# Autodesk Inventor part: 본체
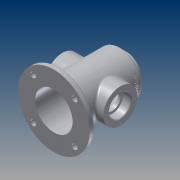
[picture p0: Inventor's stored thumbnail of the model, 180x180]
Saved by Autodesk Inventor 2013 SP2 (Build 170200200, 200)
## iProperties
Created: 2014-12
Part Number: 본체
Material: 알루미늄 6061
Document SubType Name: Modeling
Designer: CADB303
Density: 2.71 g/cm^3
Mass: 479.262 g
Surface Area: 608.932 cm^2
Volume: 176.85 cm^3
Author: CADB303
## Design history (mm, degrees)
sketch "스케치1"
  geometry: L1 (0, 53)-(0, -53); L2 (0, -53)-(-52.5, -53); L3 (-52.5, -53)-(-52.5, -45); L4 (-52.5, -45)-(-32.5, -45); L5 (-32.5, -45)-(-32.5, 45); L6 (-32.5, 45)-(-22.5, 45); L7 (-22.5, 45)-(-22.5, 53); L8 (-22.5, 53)-(0, 53); L9 (0, 40)-(-27.5, 40); L10 (-27.5, 40)-(-27.5, -53); 2 further points
  constraints: 20 end point, 6 parallel, 3 perpendicular, 2 point on line, 1 coincident, 1 midpoint, 1 vertical
  dimensions: "d0" = 106 distance of L1.start L1.end; "d2" = 98 distance between parallel lines of L6 L2; "d3" = 93 distance between parallel lines of L9 L2; "d4" = 45 diameter of L7.end L1; "d5" = 65 diameter of L5 L1; "d6" = 55 diameter of L10 L1; "d7" = 8 distance between parallel lines of L4 L2; "d8" = 105 diameter of L3 L1
revolve "회전1" sketch "스케치1" stored, may be unused: angle "d9" = 90 deg
node "작업 평면1"
sketch "스케치2"
  geometry: L1 (-53, -52.5)-(-53, 52.5) reference; C1 r 25 at (2, 0); 1 further point
  constraints: 1 centre point, 1 horizontal alignment
  dimensions: "d15" = 50 diameter of C1; "d16" = 55 distance from line of C1.centre L1
extrude "돌출1" join sketch "스케치2" stored distance "d17" = 10; taper "d18" = 0 deg
hole "구멍1" diameter "d21" = 25; stored, may be unused: countersink angle "d25" = 90 deg, drill point angle "d27" = 0 deg; dims "d19" = 10, "d20" = 10, "d22" = 6, "d23" = 32, "d24" = 12, "d26" = 20
hole "구멍2" diameter "d30" = 27; stored, may be unused: countersink angle "d34" = 90 deg, drill point angle "d36" = 0 deg; dims "d28" = 10, "d29" = 10, "d31" = 6, "d32" = 32, "d33" = 12, "d35" = 20
sketch "스케치3"
  geometry: L1 (0, 0)-(30.406, 30.406); L2 (0, 0)-(43, 0); 1 further point
  constraints: 4 end point, 1 coincident, 1 equal length, 1 horizontal
  dimensions: "d37" = 43 distance of L1.start L1.end; "d38" = 45 deg angle of L2 L1
hole "구멍3" sketch "스케치3" at (30.406, 30.406) diameter "d39" = 8; stored, may be unused: countersink angle "d43" = 90 deg, drill point angle "d45" = 0 deg; dims "d40" = 6, "d41" = 32, "d42" = 12, "d44" = 8
sketch "스케치4"
  geometry: 2 further points
  constraints: 1 vertical alignment
  dimensions: "d49" = 17.5 distance of point (0, 17.5) point (0, 0)
hole "구멍4" sketch "스케치4" at (0, 17.5) diameter "d50" = 2.459; stored, may be unused: countersink angle "d54" = 90 deg, drill point angle "d56" = 118 deg; dims "d51" = 6, "d52" = 32, "d53" = 12, "d55" = 8
sketch "스케치5"
  geometry: C1 r 12.5 at (0, 0) reference; 2 further points
  constraints: 1 vertical alignment
  dimensions: "d60" = 20.5 distance of point (0, 20.5) C1.centre
hole "구멍5" sketch "스케치5" at (0, 20.5) diameter "d61" = 2.459; stored, may be unused: countersink angle "d65" = 90 deg, drill point angle "d67" = 118 deg; dims "d62" = 6, "d63" = 4, "d64" = 2, "d66" = 8
chamfer "모따기1" distance "d72" = 1; stored, may be unused: second distance "d73" = 2, angle "d74" = 45 deg
node "작업 평면3"
sketch "스케치7"
  geometry: L1 (53, -22.5)-(53, 22.5) reference; L2 (45, -32.5)-(45, 32.5) reference; 3 further points
  constraints: 1 horizontal alignment, 1 midpoint, 1 other
  dimensions: "d78" = 9 distance from line of point (36, 0) L2
feature "엠보싱1" sketch "스케치7" dims "d0" = 106, "d2" = 98, "d3" = 93, "d4" = 45, "d5" = 65, "d6" = 55, "d7" = 8, "d8" = 105, "d23" = 32, "d79" = 1, "d80" = 0
fillet "모깎기2" dims "d81" = 3
fillet "모깎기3" dims "d82" = 0.3
node "솔리드1"
pattern_circular "원형 패턴1" dims angle "d47" = 360 deg
pattern_circular "원형 패턴2" dims angle "d58" = 360 deg
pattern_circular "원형 패턴3" dims angle "d69" = 360 deg
mirror "대칭2"
other parameters: "d10" = 42.5, "d75" = 32.5
